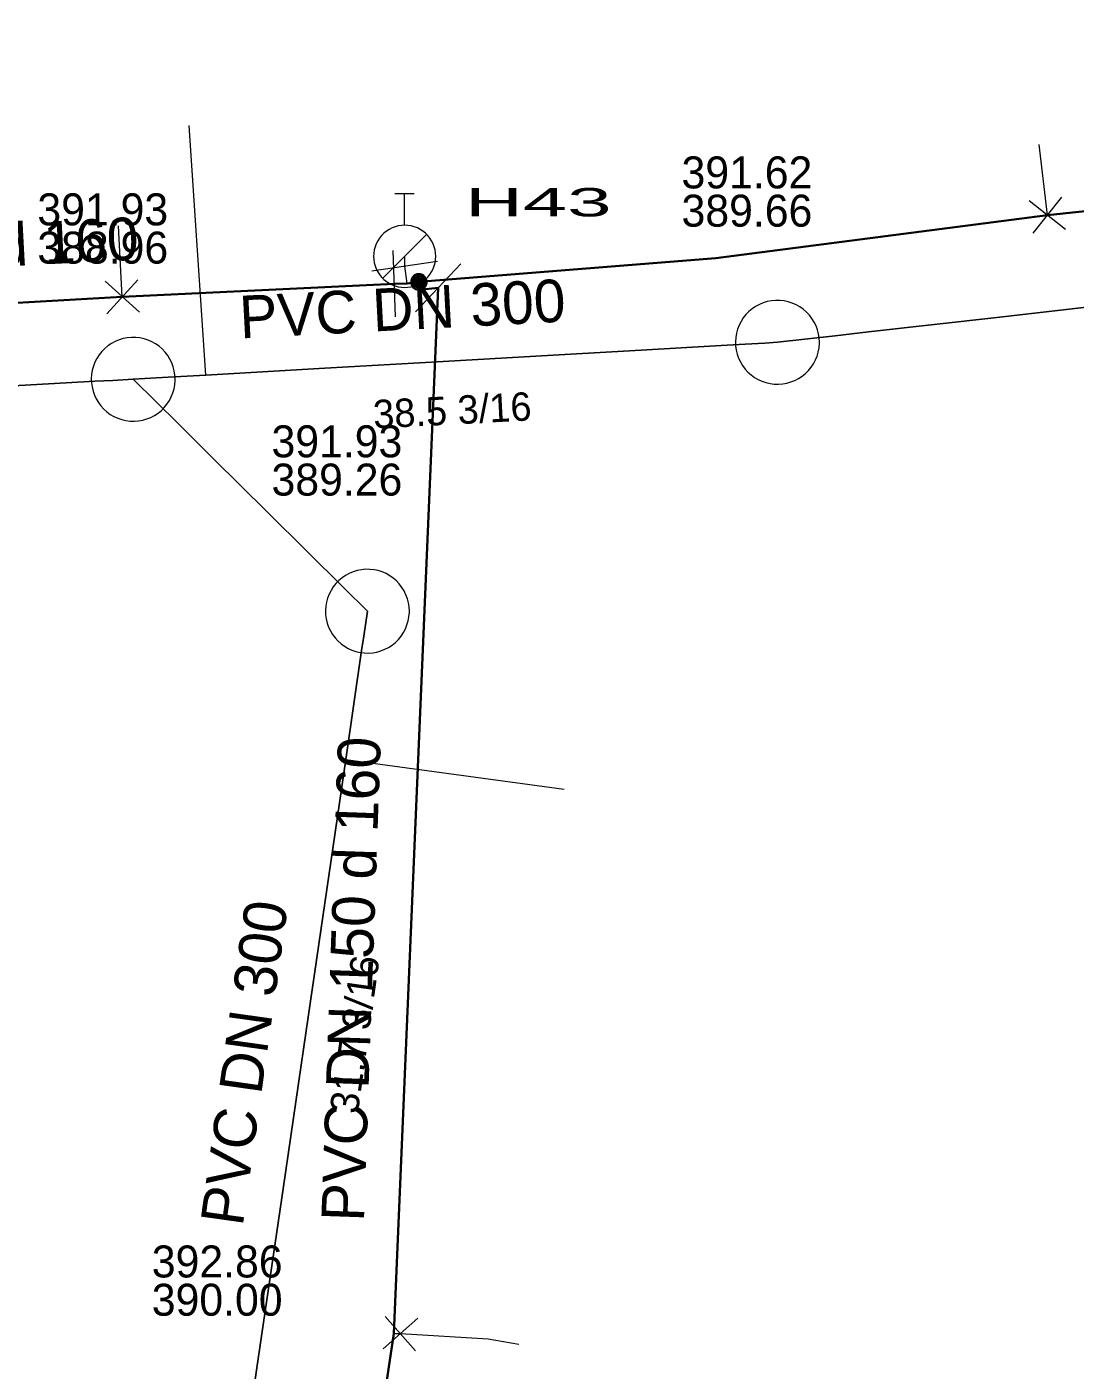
# Model space of a CAD drawing. Extents: x -772952 to -772403, y -1033777 to -1033210.
# Drawn here: x -772622.94 to -772593.44, y -1033373.41 to -1033335.59 of the extents above; entities that cross this region are included whole.
import ezdxf

# ---------------------------------------------------------------- set-up
doc = ezdxf.new("R2010")
doc.units = 0
doc.header["$LTSCALE"] = 0.36
for name, color, linetype, lineweight in [('15', 7, 'Continuous', 13), ('16', 7, 'Continuous', 35), ('2', 7, 'Continuous', 25), ('20', 7, 'Continuous', 13), ('4', 7, 'Continuous', 13), ('57', 7, 'Continuous', 13), ('59', 7, 'Continuous', 13)]:
    doc.layers.add(name, color=color, linetype=linetype, lineweight=lineweight)
for name, color, linetype in [('17', 7, 'Continuous'), ('3', 7, 'Continuous'), ('6', 7, 'Continuous')]:
    doc.layers.add(name, color=color, linetype=linetype)

msp = doc.modelspace()

# ---------------------------------------------------------------- linework, layer by layer
at = {"layer": '15'}
for p, q in [((-772593.71, -1033341.292), (-772594.732, -1033340.485)), ((-772594.619, -1033341.394), (-772593.817, -1033340.383)), ((-772612.564, -1033343.749), (-772612.635, -1033341.889)), ((-772611.389, -1033342.195), (-772613.231, -1033342.464)), ((-772612.01, -1033343.614), (-772610.728, -1033342.264)), ((-772619.777, -1033343.624), (-772620.744, -1033342.753)), ((-772620.691, -1033343.667), (-772619.825, -1033342.711)), ((-772612.859, -1033371.898), (-772612.003, -1033372.864)), ((-772612.917, -1033372.811), (-772611.944, -1033371.946))]:
    msp.add_line(p, q, dxfattribs=at)
for points in [[(-772611.679, -1033342.77), (-772611.685, -1033342.718), (-772611.702, -1033342.668), (-772611.731, -1033342.624), (-772611.768, -1033342.587), (-772611.813, -1033342.56), (-772611.863, -1033342.543), (-772611.916, -1033342.539), (-772611.968, -1033342.546), (-772612.017, -1033342.565), (-772612.06, -1033342.594), (-772612.096, -1033342.633), (-772612.122, -1033342.678), (-772612.138, -1033342.729), (-772612.141, -1033342.781), (-772612.133, -1033342.833), (-772612.113, -1033342.882), (-772612.082, -1033342.925), (-772612.043, -1033342.959), (-772611.997, -1033342.985), (-772611.946, -1033342.999), (-772611.893, -1033343.001), (-772611.842, -1033342.991), (-772611.794, -1033342.97), (-772611.751, -1033342.939), (-772611.717, -1033342.898), (-772611.693, -1033342.852), (-772611.681, -1033342.801)], [(-772611.709, -1033342.77), (-772611.715, -1033342.721), (-772611.732, -1033342.675), (-772611.76, -1033342.635), (-772611.797, -1033342.603), (-772611.841, -1033342.581), (-772611.889, -1033342.57), (-772611.938, -1033342.57), (-772611.985, -1033342.583), (-772612.028, -1033342.607), (-772612.064, -1033342.64), (-772612.091, -1033342.681), (-772612.107, -1033342.728), (-772612.111, -1033342.777), (-772612.104, -1033342.825), (-772612.085, -1033342.87), (-772612.055, -1033342.91), (-772612.017, -1033342.941), (-772611.973, -1033342.961), (-772611.925, -1033342.971), (-772611.876, -1033342.969), (-772611.829, -1033342.954), (-772611.786, -1033342.929), (-772611.752, -1033342.895), (-772611.726, -1033342.853), (-772611.712, -1033342.806)], [(-772611.739, -1033342.77), (-772611.745, -1033342.725), (-772611.762, -1033342.683), (-772611.79, -1033342.648), (-772611.826, -1033342.621), (-772611.868, -1033342.604), (-772611.913, -1033342.599), (-772611.958, -1033342.605), (-772611.999, -1033342.624), (-772612.034, -1033342.652), (-772612.061, -1033342.689), (-772612.077, -1033342.731), (-772612.081, -1033342.776), (-772612.074, -1033342.821), (-772612.055, -1033342.862), (-772612.026, -1033342.896), (-772611.989, -1033342.922), (-772611.946, -1033342.938), (-772611.901, -1033342.941), (-772611.856, -1033342.933), (-772611.816, -1033342.913), (-772611.782, -1033342.884), (-772611.756, -1033342.846), (-772611.742, -1033342.803)], [(-772611.769, -1033342.77), (-772611.774, -1033342.729), (-772611.792, -1033342.692), (-772611.819, -1033342.661), (-772611.854, -1033342.64), (-772611.894, -1033342.629), (-772611.935, -1033342.631), (-772611.974, -1033342.644), (-772612.008, -1033342.668), (-772612.033, -1033342.7), (-772612.048, -1033342.738), (-772612.051, -1033342.779), (-772612.043, -1033342.819), (-772612.023, -1033342.855), (-772611.994, -1033342.884), (-772611.957, -1033342.903), (-772611.917, -1033342.911), (-772611.876, -1033342.907), (-772611.838, -1033342.892), (-772611.806, -1033342.866), (-772611.783, -1033342.832), (-772611.77, -1033342.793)], [(-772611.799, -1033342.77), (-772611.804, -1033342.734), (-772611.822, -1033342.702), (-772611.848, -1033342.677), (-772611.882, -1033342.662), (-772611.918, -1033342.659), (-772611.953, -1033342.667), (-772611.984, -1033342.687), (-772612.007, -1033342.715), (-772612.02, -1033342.749), (-772612.02, -1033342.786), (-772612.009, -1033342.821), (-772611.988, -1033342.85), (-772611.958, -1033342.871), (-772611.923, -1033342.881), (-772611.886, -1033342.879), (-772611.852, -1033342.865), (-772611.825, -1033342.842), (-772611.806, -1033342.81), (-772611.799, -1033342.775)], [(-772611.829, -1033342.77), (-772611.834, -1033342.739), (-772611.851, -1033342.713), (-772611.877, -1033342.696), (-772611.907, -1033342.689), (-772611.938, -1033342.693), (-772611.965, -1033342.71), (-772611.983, -1033342.734), (-772611.991, -1033342.765), (-772611.987, -1033342.795), (-772611.972, -1033342.823), (-772611.948, -1033342.842), (-772611.918, -1033342.851), (-772611.887, -1033342.848), (-772611.859, -1033342.834), (-772611.839, -1033342.81), (-772611.829, -1033342.781)], [(-772611.859, -1033342.77), (-772611.864, -1033342.746), (-772611.881, -1033342.728), (-772611.904, -1033342.719), (-772611.928, -1033342.722), (-772611.949, -1033342.736), (-772611.96, -1033342.758), (-772611.96, -1033342.783), (-772611.948, -1033342.804), (-772611.928, -1033342.818), (-772611.903, -1033342.821), (-772611.88, -1033342.812), (-772611.864, -1033342.794)], [(-772611.889, -1033342.77), (-772611.894, -1033342.755), (-772611.909, -1033342.749), (-772611.924, -1033342.753), (-772611.931, -1033342.767), (-772611.927, -1033342.782), (-772611.914, -1033342.791), (-772611.899, -1033342.788), (-772611.889, -1033342.776)]]:
    msp.add_lwpolyline(points, close=True, dxfattribs=at)
at = {"layer": '16'}
for points in [[(-772611.91, -1033342.769), (-772603.55, -1033342.1), (-772594.219, -1033340.89), (-772583.71, -1033339.769), (-772575.059, -1033338.82), (-772564.48, -1033337.789), (-772553.859, -1033336.829), (-772540.23, -1033335.589)], [(-772612.6, -1033342.82), (-772612.24, -1033342.81), (-772611.91, -1033342.77)], [(-772611.37, -1033342.94), (-772611.9, -1033342.99), (-772611.91, -1033342.77)], [(-772633.819, -1033343.84), (-772631.109, -1033343.809), (-772620.26, -1033343.19), (-772612.6, -1033342.82)], [(-772611.37, -1033342.94), (-772612.62, -1033372.379), (-772613.215, -1033376.396)]]:
    msp.add_lwpolyline(points, dxfattribs=at)
at = {"layer": '2'}
for points in [[(-772601.82, -1033344.47), (-772600.191, -1033344.285), (-772599.257, -1033344.179), (-772595.643, -1033343.769), (-772592.064, -1033343.362), (-772588.473, -1033342.955), (-772585.192, -1033342.582), (-772580.597, -1033342.061), (-772580.014, -1033341.995), (-772575.604, -1033341.494), (-772574.126, -1033341.327), (-772572.39, -1033341.13)], [(-772619.95, -1033345.51), (-772618.971, -1033345.453), (-772617.907, -1033345.392), (-772614.562, -1033345.2), (-772611.23, -1033345.009), (-772608.13, -1033344.831), (-772605.657, -1033344.689), (-772603.407, -1033344.561), (-772602.728, -1033344.522), (-772602.17, -1033344.49), (-772601.82, -1033344.47)], [(-772634.23, -1033346.29), (-772633.68, -1033346.26), (-772633.531, -1033346.251), (-772632.819, -1033346.212), (-772629.247, -1033346.017), (-772625.786, -1033345.828), (-772624.992, -1033345.785), (-772621.84, -1033345.613), (-772621.027, -1033345.568), (-772620.529, -1033345.541), (-772619.95, -1033345.51)], [(-772619.95, -1033345.51), (-772619.3, -1033346.153), (-772618.708, -1033346.74), (-772617.691, -1033347.747), (-772616.182, -1033349.242), (-772615.049, -1033350.365), (-772614.054, -1033351.352), (-772613.794, -1033351.609), (-772613.586, -1033351.815), (-772613.36, -1033352.04)], [(-772613.36, -1033352.04), (-772613.463, -1033352.747), (-772613.521, -1033353.145), (-772613.969, -1033356.213), (-772614.381, -1033359.036), (-772615.085, -1033363.859), (-772615.734, -1033368.305), (-772616.142, -1033371.106), (-772616.478, -1033373.404), (-772616.576, -1033374.075), (-772616.73, -1033375.13)]]:
    msp.add_lwpolyline(points, dxfattribs=at)
at = {"layer": '20'}
for p, q in [((-772612.586, -1033340.28), (-772612.045, -1033340.28)), ((-772612.316, -1033341.164), (-772612.316, -1033340.28)), ((-772611.697, -1033341.431), (-772612.934, -1033342.669))]:
    msp.add_line(p, q, dxfattribs=at)
msp.add_lwpolyline([(-772611.436, -1033342.049), (-772611.44, -1033341.959), (-772611.454, -1033341.869), (-772611.478, -1033341.779), (-772611.51, -1033341.695), (-772611.552, -1033341.613), (-772611.602, -1033341.535), (-772611.66, -1033341.465), (-772611.724, -1033341.399), (-772611.796, -1033341.343), (-772611.872, -1033341.293), (-772611.954, -1033341.251), (-772612.04, -1033341.217), (-772612.128, -1033341.193), (-772612.218, -1033341.179), (-772612.31, -1033341.175), (-772612.402, -1033341.179), (-772612.492, -1033341.193), (-772612.58, -1033341.217), (-772612.666, -1033341.251), (-772612.748, -1033341.293), (-772612.824, -1033341.343), (-772612.896, -1033341.399), (-772612.96, -1033341.465), (-772613.018, -1033341.535), (-772613.068, -1033341.613), (-772613.11, -1033341.695), (-772613.142, -1033341.779), (-772613.166, -1033341.869), (-772613.18, -1033341.959), (-772613.186, -1033342.051), (-772613.18, -1033342.141), (-772613.166, -1033342.231), (-772613.142, -1033342.321), (-772613.11, -1033342.405), (-772613.068, -1033342.487), (-772613.018, -1033342.565), (-772612.96, -1033342.635), (-772612.896, -1033342.701), (-772612.824, -1033342.757), (-772612.748, -1033342.807), (-772612.666, -1033342.849), (-772612.58, -1033342.883), (-772612.492, -1033342.905), (-772612.402, -1033342.921), (-772612.31, -1033342.925), (-772612.218, -1033342.921), (-772612.128, -1033342.905), (-772612.04, -1033342.883), (-772611.954, -1033342.849), (-772611.872, -1033342.807), (-772611.796, -1033342.757), (-772611.724, -1033342.701), (-772611.66, -1033342.635), (-772611.602, -1033342.565), (-772611.552, -1033342.487), (-772611.51, -1033342.405), (-772611.478, -1033342.321), (-772611.454, -1033342.231), (-772611.44, -1033342.141), (-772611.436, -1033342.051)], dxfattribs=at)
at = {"layer": '4'}
for points in [[(-772600.639, -1033344.47), (-772600.646, -1033344.351), (-772600.664, -1033344.234), (-772600.693, -1033344.118), (-772600.733, -1033344.007), (-772600.786, -1033343.9), (-772600.848, -1033343.799), (-772600.921, -1033343.704), (-772601.002, -1033343.618), (-772601.093, -1033343.54), (-772601.191, -1033343.471), (-772601.294, -1033343.413), (-772601.402, -1033343.366), (-772601.517, -1033343.329), (-772601.632, -1033343.304), (-772601.75, -1033343.292), (-772601.87, -1033343.291), (-772601.989, -1033343.302), (-772602.105, -1033343.325), (-772602.218, -1033343.359), (-772602.328, -1033343.405), (-772602.433, -1033343.462), (-772602.532, -1033343.529), (-772602.622, -1033343.605), (-772602.706, -1033343.69), (-772602.779, -1033343.784), (-772602.843, -1033343.884), (-772602.897, -1033343.99), (-772602.941, -1033344.101), (-772602.973, -1033344.215), (-772602.992, -1033344.333), (-772603, -1033344.452), (-772602.995, -1033344.57), (-772602.98, -1033344.688), (-772602.951, -1033344.804), (-772602.913, -1033344.916), (-772602.862, -1033345.024), (-772602.801, -1033345.126), (-772602.73, -1033345.222), (-772602.649, -1033345.309), (-772602.561, -1033345.389), (-772602.465, -1033345.459), (-772602.362, -1033345.519), (-772602.254, -1033345.568), (-772602.141, -1033345.606), (-772602.024, -1033345.632), (-772601.907, -1033345.647), (-772601.788, -1033345.65), (-772601.669, -1033345.641), (-772601.551, -1033345.62), (-772601.438, -1033345.587), (-772601.328, -1033345.543), (-772601.222, -1033345.488), (-772601.122, -1033345.422), (-772601.029, -1033345.347), (-772600.946, -1033345.263), (-772600.87, -1033345.171), (-772600.804, -1033345.072), (-772600.749, -1033344.967), (-772600.705, -1033344.857), (-772600.671, -1033344.743), (-772600.649, -1033344.626), (-772600.639, -1033344.507)], [(-772618.769, -1033345.51), (-772618.776, -1033345.391), (-772618.794, -1033345.274), (-772618.823, -1033345.158), (-772618.864, -1033345.047), (-772618.916, -1033344.94), (-772618.978, -1033344.839), (-772619.051, -1033344.744), (-772619.132, -1033344.658), (-772619.223, -1033344.58), (-772619.321, -1033344.511), (-772619.424, -1033344.453), (-772619.532, -1033344.406), (-772619.647, -1033344.369), (-772619.762, -1033344.344), (-772619.88, -1033344.332), (-772620, -1033344.331), (-772620.119, -1033344.342), (-772620.235, -1033344.365), (-772620.348, -1033344.399), (-772620.458, -1033344.445), (-772620.563, -1033344.502), (-772620.662, -1033344.569), (-772620.752, -1033344.645), (-772620.836, -1033344.73), (-772620.909, -1033344.824), (-772620.973, -1033344.924), (-772621.027, -1033345.03), (-772621.071, -1033345.141), (-772621.103, -1033345.255), (-772621.122, -1033345.373), (-772621.13, -1033345.492), (-772621.125, -1033345.61), (-772621.11, -1033345.728), (-772621.081, -1033345.844), (-772621.043, -1033345.956), (-772620.992, -1033346.064), (-772620.931, -1033346.166), (-772620.86, -1033346.262), (-772620.779, -1033346.349), (-772620.691, -1033346.429), (-772620.595, -1033346.499), (-772620.492, -1033346.559), (-772620.384, -1033346.608), (-772620.271, -1033346.646), (-772620.154, -1033346.672), (-772620.037, -1033346.687), (-772619.918, -1033346.69), (-772619.799, -1033346.681), (-772619.681, -1033346.66), (-772619.568, -1033346.627), (-772619.458, -1033346.583), (-772619.352, -1033346.528), (-772619.252, -1033346.462), (-772619.159, -1033346.387), (-772619.076, -1033346.303), (-772619, -1033346.211), (-772618.934, -1033346.112), (-772618.879, -1033346.007), (-772618.835, -1033345.897), (-772618.801, -1033345.783), (-772618.779, -1033345.666), (-772618.769, -1033345.547)], [(-772612.179, -1033352.04), (-772612.186, -1033351.921), (-772612.204, -1033351.804), (-772612.233, -1033351.688), (-772612.274, -1033351.577), (-772612.326, -1033351.47), (-772612.389, -1033351.369), (-772612.462, -1033351.274), (-772612.543, -1033351.188), (-772612.633, -1033351.11), (-772612.731, -1033351.041), (-772612.834, -1033350.983), (-772612.943, -1033350.936), (-772613.057, -1033350.899), (-772613.173, -1033350.874), (-772613.291, -1033350.862), (-772613.41, -1033350.861), (-772613.529, -1033350.872), (-772613.645, -1033350.895), (-772613.759, -1033350.929), (-772613.869, -1033350.975), (-772613.973, -1033351.032), (-772614.072, -1033351.099), (-772614.163, -1033351.175), (-772614.246, -1033351.26), (-772614.32, -1033351.354), (-772614.384, -1033351.454), (-772614.438, -1033351.56), (-772614.481, -1033351.671), (-772614.513, -1033351.785), (-772614.532, -1033351.903), (-772614.54, -1033352.022), (-772614.536, -1033352.14), (-772614.52, -1033352.258), (-772614.492, -1033352.374), (-772614.453, -1033352.486), (-772614.402, -1033352.594), (-772614.341, -1033352.696), (-772614.27, -1033352.792), (-772614.19, -1033352.879), (-772614.101, -1033352.959), (-772614.005, -1033353.029), (-772613.902, -1033353.089), (-772613.794, -1033353.138), (-772613.681, -1033353.176), (-772613.565, -1033353.202), (-772613.447, -1033353.217), (-772613.328, -1033353.22), (-772613.21, -1033353.211), (-772613.092, -1033353.19), (-772612.978, -1033353.157), (-772612.868, -1033353.113), (-772612.762, -1033353.058), (-772612.663, -1033352.992), (-772612.57, -1033352.917), (-772612.486, -1033352.833), (-772612.411, -1033352.741), (-772612.345, -1033352.642), (-772612.289, -1033352.537), (-772612.245, -1033352.427), (-772612.211, -1033352.313), (-772612.19, -1033352.196), (-772612.179, -1033352.077)]]:
    msp.add_lwpolyline(points, close=True, dxfattribs=at)
at = {"layer": '57'}
for p, q in [((-772617.907, -1033345.392), (-772618.38, -1033338.37)), ((-772613.969, -1033356.213), (-772607.82, -1033357.05))]:
    msp.add_line(p, q, dxfattribs=at)
at = {"layer": '59'}
for p, q in [((-772594.219, -1033340.89), (-772594.454, -1033338.903)), ((-772620.26, -1033343.19), (-772620.364, -1033341.193))]:
    msp.add_line(p, q, dxfattribs=at)
for points in [[(-772612.24, -1033342.81), (-772612.31, -1033342.33), (-772612.31, -1033342.05)], [(-772612.621, -1033372.38), (-772612.432, -1033372.38), (-772609.959, -1033372.522), (-772609.093, -1033372.672)]]:
    msp.add_lwpolyline(points, dxfattribs=at)

# ---------------------------------------------------------------- texts
at = {"layer": '17'}
for s, rotation, p in [('PE DN 150 d 160 ', 3, (-772632.245, -1033342.79)), ('PVC DN 150 d 160', 88, (-772613.458, -1033369.237))]:
    msp.add_text(s, height=1.2, rotation=rotation, dxfattribs=at).set_placement(p)
at = {"layer": '20', "width": 2.1}
msp.add_text('H43 ', height=0.8, dxfattribs=at).set_placement((-772610.609, -1033340.926))
at = {"layer": '3'}
for s, height, rotation, p in [('PVC DN 300', 1.2, 3, (-772616.931, -1033344.363)), ('38.5 3/16', 0.8, 3, (-772613.178, -1033346.899)), ('PVC DN 300', 1.2, 82, (-772616.871, -1033369.382)), ('31.7 3/16', 0.8, 82, (-772613.633, -1033366.215))]:
    msp.add_text(s, height=height, rotation=rotation, dxfattribs=at).set_placement(p)
at = {"layer": '6'}
for s, p in [('391.62', (-772604.518, -1033340.137)), ('391.93', (-772622.648, -1033341.177)), ('389.66', (-772604.518, -1033341.214)), ('388.96', (-772622.648, -1033342.254)), ('391.93', (-772616.058, -1033347.708)), ('389.26', (-772616.058, -1033348.785)), ('392.86', (-772619.428, -1033370.798)), ('390.00', (-772619.428, -1033371.875))]:
    msp.add_text(s, height=0.9, dxfattribs=at).set_placement(p)

doc.saveas('drawing.dxf')
